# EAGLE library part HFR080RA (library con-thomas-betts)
THOMAS&BETTS
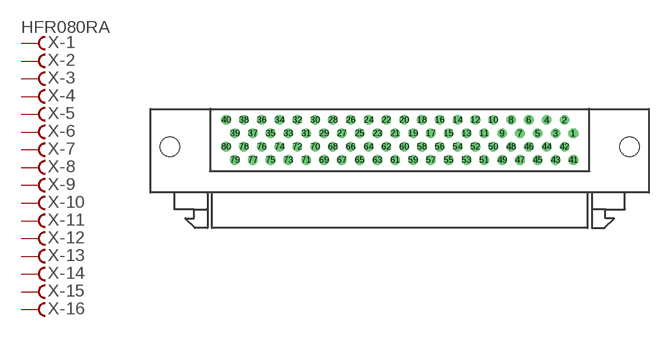
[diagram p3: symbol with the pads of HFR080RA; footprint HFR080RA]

Designator prefix X; gates -1=FV -2=F -3=F -4=F -5=F -6=F -7=F -8=F -9=F -10=F -11=F -12=F -13=F -14=F -15=F -16=F -17=F -18=F -19=F -20=F -21=F -22=F -23=F -24=F -25=F -26=F -27=F -28=F -29=F -30=F -31=F -32=F -33=F -34=F -35=F -36=F -37=F -38=F -39=F -40=F -42=F -43=F -44=F -45=F -46=F -47=F -48=F -49=F -50=F -51=F -52=F -53=F -54=F -55=F -56=F -57=F -58=F -59=F -60=F -61=F -62=F -63=F -64=F -65=F -66=F -67=F -68=F -69=F -70=F -71=F -72=F -73=F -74=F -75=F -76=F -77=F -78=F -79=F -80=F -41=F

## HFR080RA (OC_FARNELL: unknown; OC_NEWARK: unknown)  [HFR080RA]
1  -1:F  pas
2  -2:F  pas
3  -3:F  pas
4  -4:F  pas
5  -5:F  pas
6  -6:F  pas
7  -7:F  pas
8  -8:F  pas
9  -9:F  pas
10  -10:F  pas
11  -11:F  pas
12  -12:F  pas
13  -13:F  pas
14  -14:F  pas
15  -15:F  pas
16  -16:F  pas
17  -17:F  pas
18  -18:F  pas
19  -19:F  pas
20  -20:F  pas
21  -21:F  pas
22  -22:F  pas
23  -23:F  pas
24  -24:F  pas
25  -25:F  pas
26  -26:F  pas
27  -27:F  pas
28  -28:F  pas
29  -29:F  pas
30  -30:F  pas
31  -31:F  pas
32  -32:F  pas
33  -33:F  pas
34  -34:F  pas
35  -35:F  pas
36  -36:F  pas
37  -37:F  pas
38  -38:F  pas
39  -39:F  pas
40  -40:F  pas
41  -41:F  pas
42  -42:F  pas
43  -43:F  pas
44  -44:F  pas
45  -45:F  pas
46  -46:F  pas
47  -47:F  pas
48  -48:F  pas
49  -49:F  pas
50  -50:F  pas
51  -51:F  pas
52  -52:F  pas
53  -53:F  pas
54  -54:F  pas
55  -55:F  pas
56  -56:F  pas
57  -57:F  pas
58  -58:F  pas
59  -59:F  pas
60  -60:F  pas
61  -61:F  pas
62  -62:F  pas
63  -63:F  pas
64  -64:F  pas
65  -65:F  pas
66  -66:F  pas
67  -67:F  pas
68  -68:F  pas
69  -69:F  pas
70  -70:F  pas
71  -71:F  pas
72  -72:F  pas
73  -73:F  pas
74  -74:F  pas
75  -75:F  pas
76  -76:F  pas
77  -77:F  pas
78  -78:F  pas
79  -79:F  pas
80  -80:F  pas

## Footprint HFR080RA (pad centres in mm)
THOMAS&BETTS Fine Pitch "D" Connector HFR080RA29xxx
drill 0.864 octagon: 1 24.765,6.98
drill 0.864 round: 2 23.495,8.89; 3 22.225,6.98; 4 20.955,8.89; 5 19.685,6.98; 6 18.415,8.89; 7 17.145,6.98; 8 15.875,8.89; 9 14.605,6.98; 10 13.335,8.89; 11 12.065,6.98; 12 10.795,8.89; 13 9.525,6.98; 14 8.255,8.89; 15 6.985,6.98; 16 5.715,8.89; 17 4.445,6.98; 18 3.175,8.89; 19 1.905,6.98; 20 0.635,8.89; 21 -0.635,6.98; 22 -1.905,8.89; 23 -3.175,6.98; 24 -4.445,8.89; 25 -5.715,6.98; 26 -6.985,8.89; 27 -8.255,6.98; 28 -9.525,8.89; 29 -10.795,6.98; 30 -12.065,8.89; 31 -13.335,6.98; 32 -14.605,8.89; 33 -15.875,6.98; 34 -17.145,8.89; 35 -18.415,6.98; 36 -19.685,8.89; 37 -20.955,6.98; 38 -22.225,8.89; 39 -23.495,6.98; 40 -24.765,8.89; 41 24.765,3.17; 42 23.495,5.07; 43 22.225,3.17; 44 20.955,5.07; 45 19.685,3.17; 46 18.415,5.07; 47 17.145,3.17; 48 15.875,5.07; 49 14.605,3.17; 50 13.335,5.07; 51 12.065,3.17; 52 10.795,5.07; 53 9.525,3.17; 54 8.255,5.07; 55 6.985,3.17; 56 5.715,5.07; 57 4.445,3.17; 58 3.175,5.07; 59 1.905,3.17; 60 0.635,5.07; 61 -0.635,3.17; 62 -1.905,5.07; 63 -3.175,3.17; 64 -4.445,5.07; 65 -5.715,3.17; 66 -6.985,5.07; 67 -8.255,3.17; 68 -9.525,5.07; 69 -10.795,3.17; 70 -12.065,5.07; 71 -13.335,3.17; 72 -14.605,5.07; 73 -15.875,3.17; 74 -17.145,5.07; 75 -18.415,3.17; 76 -19.685,5.07; 77 -20.955,3.17; 78 -22.225,5.07; 79 -23.495,3.17; 80 -24.765,5.07
hole 2.769 at 32.766,5.07
hole 2.769 at -32.766,5.07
